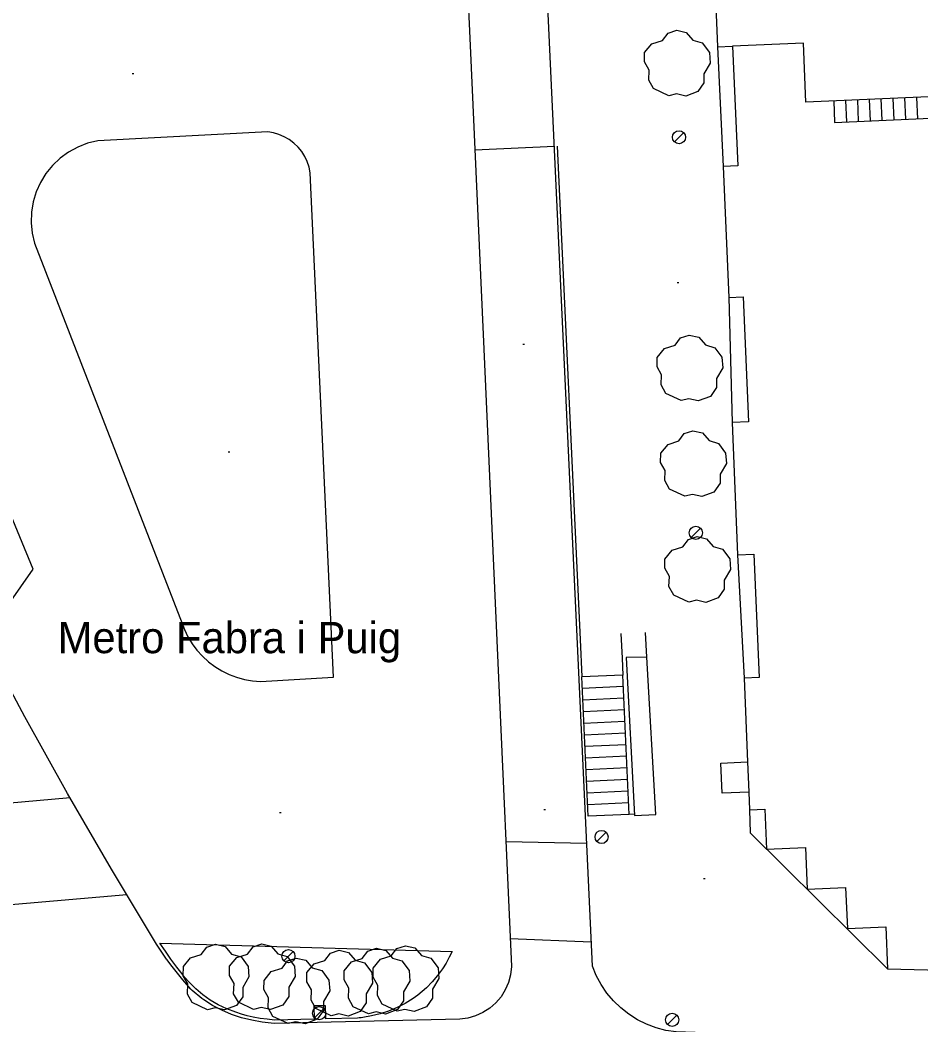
# Model space of a CAD drawing. Extents: x 431390 to 432653, y 4586754 to 4589600.
# Drawn here: x 431745 to 431799.8, y 4586844.3 to 4586905.4 of the extents above; entities that cross this region are included whole.
import ezdxf

# ---------------------------------------------------------------- set-up
doc = ezdxf.new("R2010")
doc.units = 0
for name, color, linetype in [('COM_17LS_LN', 7, 'Continuous'), ('COM_51_LN', 7, 'Continuous'), ('CON_01_LN', 7, 'Continuous'), ('CON_01FI_LN', 7, 'Continuous'), ('CON_04_LN', 7, 'Continuous'), ('CON_07_LN', 7, 'Continuous'), ('CON_14LS_LN', 7, 'Continuous'), ('CON_15_LN', 7, 'Continuous'), ('CON_20_LN', 7, 'Continuous'), ('CON_23_LN', 7, 'Continuous'), ('CON_34_LN', 7, 'Continuous'), ('ENE_06_PT', 7, 'Continuous'), ('ORO_03_PT', 7, 'Continuous'), ('TOP_17_TX', 7, 'Continuous'), ('VEG_03_PT', 7, 'Continuous'), ('VEG_06_LN', 7, 'Continuous')]:
    doc.layers.add(name, color=color, linetype=linetype)

msp = doc.modelspace()

# ---------------------------------------------------------------- linework, layer by layer
at = {"layer": 'COM_17LS_LN'}
for points in [[(431796.36, 4586843.5), (431784.88, 4586843.889), (431784.266, 4586843.982), (431783.664, 4586844.138), (431783.082, 4586844.355), (431782.526, 4586844.631), (431782.001, 4586844.962), (431781.512, 4586845.346), (431781.066, 4586845.778), (431780.667, 4586846.254), (431780.319, 4586846.768), (431780.025, 4586847.315), (431779.79, 4586847.89), (431777, 4586908.02), (431777.16, 4586908.53), (431779.16, 4586910.16), (431781.124, 4586911.301), (431783.707, 4586912.802), (431781.939, 4586952.061), (431780.022, 4586994.644), (431779.988, 4586995.394)], [(431772.015, 4586911.246), (431772.306, 4586904.782), (431773.178, 4586885.42), (431774.079, 4586865.422), (431774.87, 4586847.86), (431774.815, 4586847.373), (431774.688, 4586846.899), (431774.493, 4586846.449), (431774.234, 4586846.032), (431773.917, 4586845.658), (431773.548, 4586845.335), (431773.135, 4586845.069), (431772.688, 4586844.867), (431772.216, 4586844.733), (431771.73, 4586844.67), (431760.432, 4586844.413), (431759.699, 4586844.486), (431759.07, 4586844.597), (431758.451, 4586844.755), (431757.846, 4586844.959), (431757.258, 4586845.208), (431756.691, 4586845.501), (431756.147, 4586845.835), (431756.034, 4586845.917), (431755.453, 4586846.402), (431755.371, 4586846.491), (431755.117, 4586846.777), (431754.868, 4586847.067), (431754.625, 4586847.362), (431754.387, 4586847.662), (431754.154, 4586847.965), (431753.927, 4586848.273), (431753.889, 4586848.326), (431753.28, 4586849.22), (431750.536, 4586853.787), (431747.867, 4586858.398), (431745.275, 4586863.053), (431742.76, 4586867.75), (431745.78, 4586872.04), (431735.5, 4586896.92)], [(431764.04, 4586865.47), (431762.624, 4586896.15), (431762.556, 4586896.495), (431762.446, 4586896.828), (431762.296, 4586897.146), (431762.109, 4586897.443), (431761.887, 4586897.715), (431761.634, 4586897.958), (431761.353, 4586898.169), (431761.048, 4586898.343), (431760.725, 4586898.48), (431760.387, 4586898.576), (431760.04, 4586898.63), (431749.7, 4586898.09), (431749.081, 4586897.941), (431748.487, 4586897.713), (431747.928, 4586897.41), (431747.413, 4586897.037), (431746.95, 4586896.6), (431746.548, 4586896.107), (431746.214, 4586895.566), (431745.952, 4586894.986), (431745.768, 4586894.377), (431745.665, 4586893.749), (431745.644, 4586893.113), (431745.706, 4586892.48), (431745.85, 4586891.86), (431754.97, 4586868.37), (431755.185, 4586867.926), (431755.44, 4586867.504), (431755.735, 4586867.109), (431756.065, 4586866.743), (431756.429, 4586866.41), (431756.823, 4586866.113), (431757.243, 4586865.855), (431757.686, 4586865.637), (431758.147, 4586865.463), (431758.622, 4586865.333), (431759.108, 4586865.248), (431759.6, 4586865.21), (431764.04, 4586865.47)]]:
    msp.add_lwpolyline(points, dxfattribs=at)
at = {"layer": 'COM_51_LN'}
for points in [[(431777.476, 4586897.755), (431772.633, 4586897.53)], [(431732.968, 4586856.803), (431748.016, 4586858.141)], [(431779.444, 4586855.342), (431774.528, 4586855.454)], [(431751.467, 4586852.237), (431736.423, 4586850.936)], [(431779.722, 4586849.352), (431774.794, 4586849.555)]]:
    msp.add_lwpolyline(points, dxfattribs=at)
at = {"layer": 'CON_01_LN'}
for points in [[(431787.067, 4586911.66), (431787.396, 4586903.811)], [(431787.751, 4586896.533), (431788.085, 4586888.57)], [(431788.282, 4586880.964), (431788.619, 4586872.908)], [(431797.74, 4586847.72), (431865.2, 4586846.04), (431863.106, 4586867.117)], [(431789.012, 4586865.411), (431789.227, 4586860.313)], [(431789.304, 4586858.483), (431789.35, 4586857.39)]]:
    msp.add_lwpolyline(points, dxfattribs=at)
at = {"layer": 'CON_01FI_LN'}
for points in [[(431787.396, 4586903.811), (431788.322, 4586903.85), (431788.627, 4586896.57), (431787.751, 4586896.533)], [(431788.085, 4586888.57), (431788.96, 4586888.607), (431789.278, 4586881.006), (431788.282, 4586880.964)], [(431788.619, 4586872.908), (431789.616, 4586872.95), (431789.93, 4586865.45), (431789.012, 4586865.411)], [(431789.227, 4586860.313), (431789.304, 4586858.483)], [(431789.35, 4586857.39), (431790.288, 4586857.43), (431790.39, 4586855.01), (431792.743, 4586855.109), (431792.85, 4586852.57), (431795.195, 4586852.669), (431795.3, 4586850.18), (431797.632, 4586850.278), (431797.74, 4586847.72)]]:
    msp.add_lwpolyline(points, dxfattribs=at)
at = {"layer": 'CON_04_LN'}
msp.add_lwpolyline([(431804.438, 4586900.95), (431792.778, 4586900.442), (431792.621, 4586904.037), (431788.322, 4586903.85)], dxfattribs=at)
at = {"layer": 'CON_07_LN'}
msp.add_lwpolyline([(431789.304, 4586858.483), (431787.686, 4586858.415), (431787.609, 4586860.245), (431789.227, 4586860.313)], dxfattribs=at)
at = {"layer": 'CON_14LS_LN'}
msp.add_lwpolyline([(431782.338, 4586857.136), (431782.034, 4586857.122)], dxfattribs=at)
at = {"layer": 'CON_15_LN'}
for points in [[(431787.396, 4586903.811), (431787.751, 4586896.533)], [(431788.085, 4586888.57), (431788.282, 4586880.964)], [(431788.619, 4586872.908), (431789.012, 4586865.411)], [(431789.35, 4586857.39), (431789.385, 4586855.995), (431797.74, 4586847.72)]]:
    msp.add_lwpolyline(points, dxfattribs=at)
at = {"layer": 'CON_20_LN'}
for points in [[(431777.656, 4586897.763), (431779.048, 4586867.767), (431779.144, 4586865.483)], [(431781.525, 4586868.124), (431781.594, 4586866.619), (431781.641, 4586865.599)], [(431783.092, 4586866.688), (431783.022, 4586868.193)]]:
    msp.add_lwpolyline(points, dxfattribs=at)
at = {"layer": 'CON_23_LN'}
for points in [[(431794.467, 4586900.516), (431794.524, 4586899.217), (431801.717, 4586899.53), (431801.66, 4586900.829)], [(431797.344, 4586900.641), (431797.401, 4586899.342)], [(431798.063, 4586900.672), (431798.12, 4586899.373)], [(431798.783, 4586900.704), (431798.839, 4586899.405)], [(431799.502, 4586900.735), (431799.559, 4586899.436)], [(431795.186, 4586900.547), (431795.243, 4586899.248)], [(431795.906, 4586900.578), (431795.962, 4586899.28)], [(431796.625, 4586900.61), (431796.681, 4586899.311)], [(431781.641, 4586865.599), (431779.144, 4586865.483)], [(431782.034, 4586857.122), (431779.537, 4586857.006), (431779.144, 4586865.483)], [(431782.034, 4586857.122), (431781.641, 4586865.599)], [(431781.674, 4586864.893), (431779.177, 4586864.777)], [(431781.707, 4586864.186), (431779.21, 4586864.07)], [(431781.739, 4586863.48), (431779.242, 4586863.364)], [(431781.772, 4586862.773), (431779.275, 4586862.658)], [(431781.805, 4586862.067), (431779.308, 4586861.951)], [(431781.838, 4586861.36), (431779.34, 4586861.245)], [(431781.87, 4586860.654), (431779.373, 4586860.538)], [(431781.903, 4586859.948), (431779.406, 4586859.832)], [(431781.936, 4586859.241), (431779.439, 4586859.125)], [(431781.968, 4586858.535), (431779.471, 4586858.419)], [(431782.001, 4586857.828), (431779.504, 4586857.713)]]:
    msp.add_lwpolyline(points, dxfattribs=at)
at = {"layer": 'CON_34_LN'}
msp.add_lwpolyline([(431783.092, 4586866.688), (431781.838, 4586866.664), (431782.342, 4586857.053), (431783.648, 4586857.122), (431783.092, 4586866.688)], dxfattribs=at)
at = {"layer": 'ENE_06_PT'}
for p, q in [((431785.342, 4586898.592), (431784.776, 4586898.026)), ((431786.362, 4586874.532), (431785.796, 4586873.966)), ((431780.632, 4586856.032), (431780.066, 4586855.466)), ((431761.582, 4586848.782), (431761.016, 4586848.216)), ((431763.452, 4586845.312), (431762.886, 4586844.746)), ((431784.922, 4586844.912), (431784.356, 4586844.346))]:
    msp.add_line(p, q, dxfattribs=at)
for centre in [(431785.059, 4586898.309), (431786.079, 4586874.249), (431780.349, 4586855.749), (431761.299, 4586848.499), (431763.169, 4586845.029), (431784.639, 4586844.629)]:
    msp.add_circle(centre, 0.4, dxfattribs=at)
at = {"layer": 'ORO_03_PT'}
for p, q in [((431751.79, 4586902.18), (431751.89, 4586902.18)), ((431784.95, 4586889.47), (431785.05, 4586889.47)), ((431775.568, 4586885.716), (431775.668, 4586885.716)), ((431757.63, 4586879.18), (431757.73, 4586879.18)), ((431760.75, 4586857.24), (431760.85, 4586857.24)), ((431776.843, 4586857.413), (431776.943, 4586857.413)), ((431786.55, 4586853.23), (431786.65, 4586853.23))]:
    msp.add_line(p, q, dxfattribs=at)
at = {"layer": 'VEG_03_PT'}
for points in [[(431784.434, 4586900.831), (431783.507, 4586901.266), (431783.219, 4586901.787), (431783.242, 4586902.401), (431782.96, 4586902.893), (431782.968, 4586903.456), (431783.409, 4586903.991), (431784.062, 4586904.195), (431784.397, 4586904.646), (431784.923, 4586904.816), (431785.503, 4586904.683), (431785.903, 4586904.217), (431786.477, 4586904.047), (431786.911, 4586903.464), (431786.96, 4586902.822), (431786.577, 4586902.175), (431786.577, 4586901.625), (431786.205, 4586901.091), (431785.466, 4586900.816), (431784.901, 4586900.944), (431784.434, 4586900.831)], [(431785.194, 4586882.291), (431784.267, 4586882.726), (431783.979, 4586883.247), (431784.002, 4586883.861), (431783.72, 4586884.353), (431783.728, 4586884.916), (431784.169, 4586885.451), (431784.822, 4586885.655), (431785.157, 4586886.106), (431785.683, 4586886.276), (431786.263, 4586886.143), (431786.663, 4586885.677), (431787.237, 4586885.507), (431787.671, 4586884.924), (431787.72, 4586884.282), (431787.337, 4586883.635), (431787.337, 4586883.085), (431786.965, 4586882.551), (431786.226, 4586882.276), (431785.661, 4586882.404), (431785.194, 4586882.291)], [(431785.414, 4586876.471), (431784.487, 4586876.906), (431784.199, 4586877.427), (431784.222, 4586878.041), (431783.94, 4586878.533), (431783.948, 4586879.096), (431784.389, 4586879.631), (431785.042, 4586879.835), (431785.377, 4586880.286), (431785.903, 4586880.456), (431786.483, 4586880.323), (431786.883, 4586879.857), (431787.457, 4586879.687), (431787.891, 4586879.104), (431787.94, 4586878.462), (431787.557, 4586877.815), (431787.557, 4586877.265), (431787.185, 4586876.731), (431786.446, 4586876.456), (431785.881, 4586876.584), (431785.414, 4586876.471)], [(431785.664, 4586870.031), (431784.737, 4586870.466), (431784.449, 4586870.987), (431784.472, 4586871.601), (431784.19, 4586872.093), (431784.198, 4586872.656), (431784.639, 4586873.191), (431785.292, 4586873.395), (431785.627, 4586873.846), (431786.153, 4586874.016), (431786.733, 4586873.883), (431787.133, 4586873.417), (431787.707, 4586873.247), (431788.141, 4586872.664), (431788.19, 4586872.022), (431787.807, 4586871.375), (431787.807, 4586870.825), (431787.435, 4586870.291), (431786.696, 4586870.016), (431786.131, 4586870.144), (431785.664, 4586870.031)], [(431756.374, 4586845.241), (431755.447, 4586845.676), (431755.159, 4586846.197), (431755.182, 4586846.811), (431754.9, 4586847.303), (431754.908, 4586847.866), (431755.349, 4586848.401), (431756.002, 4586848.605), (431756.337, 4586849.056), (431756.863, 4586849.226), (431757.443, 4586849.093), (431757.843, 4586848.627), (431758.417, 4586848.457), (431758.851, 4586847.874), (431758.9, 4586847.232), (431758.517, 4586846.585), (431758.517, 4586846.035), (431758.145, 4586845.501), (431757.406, 4586845.226), (431756.841, 4586845.354), (431756.374, 4586845.241)], [(431759.184, 4586845.261), (431758.257, 4586845.696), (431757.969, 4586846.217), (431757.992, 4586846.831), (431757.71, 4586847.323), (431757.718, 4586847.886), (431758.159, 4586848.421), (431758.812, 4586848.625), (431759.147, 4586849.076), (431759.673, 4586849.246), (431760.253, 4586849.113), (431760.653, 4586848.647), (431761.227, 4586848.477), (431761.661, 4586847.894), (431761.71, 4586847.252), (431761.327, 4586846.605), (431761.327, 4586846.055), (431760.955, 4586845.521), (431760.216, 4586845.246), (431759.651, 4586845.374), (431759.184, 4586845.261)], [(431763.894, 4586844.871), (431762.967, 4586845.306), (431762.679, 4586845.827), (431762.702, 4586846.441), (431762.42, 4586846.933), (431762.428, 4586847.496), (431762.869, 4586848.031), (431763.522, 4586848.235), (431763.857, 4586848.686), (431764.383, 4586848.856), (431764.963, 4586848.723), (431765.363, 4586848.257), (431765.937, 4586848.087), (431766.371, 4586847.504), (431766.42, 4586846.862), (431766.037, 4586846.215), (431766.037, 4586845.665), (431765.665, 4586845.131), (431764.926, 4586844.856), (431764.361, 4586844.984), (431763.894, 4586844.871)], [(431766.164, 4586844.991), (431765.237, 4586845.426), (431764.949, 4586845.947), (431764.972, 4586846.561), (431764.69, 4586847.053), (431764.698, 4586847.616), (431765.139, 4586848.151), (431765.792, 4586848.355), (431766.127, 4586848.806), (431766.653, 4586848.976), (431767.233, 4586848.843), (431767.633, 4586848.377), (431768.207, 4586848.207), (431768.641, 4586847.624), (431768.69, 4586846.982), (431768.307, 4586846.335), (431768.307, 4586845.785), (431767.935, 4586845.251), (431767.196, 4586844.976), (431766.631, 4586845.104), (431766.164, 4586844.991)], [(431767.924, 4586845.151), (431766.997, 4586845.586), (431766.709, 4586846.107), (431766.732, 4586846.721), (431766.45, 4586847.213), (431766.458, 4586847.776), (431766.899, 4586848.311), (431767.552, 4586848.515), (431767.887, 4586848.966), (431768.413, 4586849.136), (431768.993, 4586849.003), (431769.393, 4586848.537), (431769.967, 4586848.367), (431770.401, 4586847.784), (431770.45, 4586847.142), (431770.067, 4586846.495), (431770.067, 4586845.945), (431769.695, 4586845.411), (431768.956, 4586845.136), (431768.391, 4586845.264), (431767.924, 4586845.151)], [(431761.284, 4586844.401), (431760.357, 4586844.836), (431760.069, 4586845.357), (431760.092, 4586845.971), (431759.81, 4586846.463), (431759.818, 4586847.026), (431760.259, 4586847.561), (431760.912, 4586847.765), (431761.247, 4586848.216), (431761.773, 4586848.386), (431762.353, 4586848.253), (431762.753, 4586847.787), (431763.327, 4586847.617), (431763.761, 4586847.034), (431763.81, 4586846.392), (431763.427, 4586845.745), (431763.427, 4586845.195), (431763.055, 4586844.661), (431762.316, 4586844.386), (431761.751, 4586844.514), (431761.284, 4586844.401)]]:
    msp.add_lwpolyline(points, dxfattribs=at)
at = {"layer": 'VEG_06_LN'}
msp.add_lwpolyline([(431771.27, 4586848.79), (431771.079, 4586848.435), (431770.887, 4586848.08), (431770.677, 4586847.738), (431770.377, 4586847.329), (431770.047, 4586846.94), (431769.691, 4586846.578), (431769.433, 4586846.345), (431769.164, 4586846.125), (431768.884, 4586845.92), (431768.41, 4586845.623), (431767.911, 4586845.367), (431767.395, 4586845.152), (431766.886, 4586844.988), (431766.363, 4586844.863), (431765.834, 4586844.771), (431765.72, 4586844.756), (431765.606, 4586844.742), (431765.492, 4586844.728), (431763.574, 4586844.684), (431763.56, 4586845.47), (431762.85, 4586845.47), (431762.874, 4586844.669), (431760.451, 4586844.612), (431760.014, 4586844.663), (431759.578, 4586844.714), (431759.146, 4586844.787), (431758.792, 4586844.871), (431758.441, 4586844.971), (431758.095, 4586845.086), (431757.557, 4586845.295), (431757.033, 4586845.541), (431756.537, 4586845.83), (431756.088, 4586846.154), (431755.664, 4586846.518), (431755.268, 4586846.909), (431755.003, 4586847.206), (431754.753, 4586847.517), (431754.508, 4586847.833), (431754.155, 4586848.31), (431753.816, 4586848.798), (431753.477, 4586849.285), (431771.27, 4586848.79)], dxfattribs=at)

# ---------------------------------------------------------------- texts
at = {"layer": 'TOP_17_TX'}
msp.add_text('Metro Fabra i Puig', height=1.9, dxfattribs=at).set_placement((431747.26, 4586866.927))

doc.saveas('drawing.dxf')
